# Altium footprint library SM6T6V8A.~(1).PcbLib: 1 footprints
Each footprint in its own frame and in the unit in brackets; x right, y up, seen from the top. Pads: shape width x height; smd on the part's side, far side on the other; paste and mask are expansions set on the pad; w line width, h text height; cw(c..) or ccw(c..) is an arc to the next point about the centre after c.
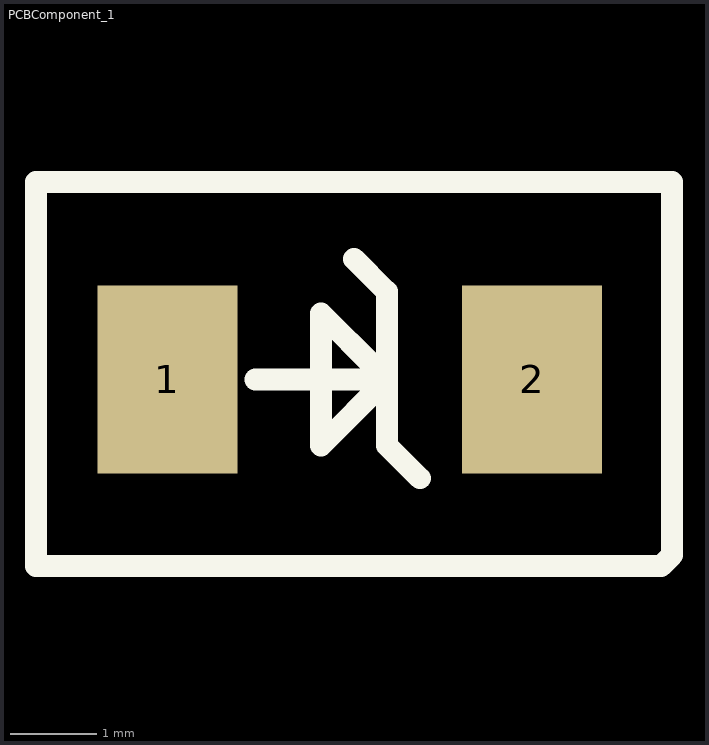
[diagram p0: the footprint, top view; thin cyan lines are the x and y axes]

## PCBComponent_1 [mm]
pads (2):
  rect 1.62x2.18 all layers, no hole: 1(-775.716,-947.293) 2(-771.496,-947.293)
Top Overlay:
  lines w0.254: -774.7,-947.293 -773.43,-947.293 ; -773.557,-945.896 -773.176,-946.277 -773.176,-946.404 -773.176,-948.055 -772.795,-948.436 ; -777.24,-949.452 -777.24,-945.007 -769.874,-945.007 -769.874,-949.325 -770.001,-949.452 -777.24,-949.452 ; -773.938,-948.055 -773.176,-947.293 -773.176,-947.166 -773.303,-947.166 -773.938,-946.531 -773.938,-948.055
